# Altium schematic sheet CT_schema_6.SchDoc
size 255 x 159 mm
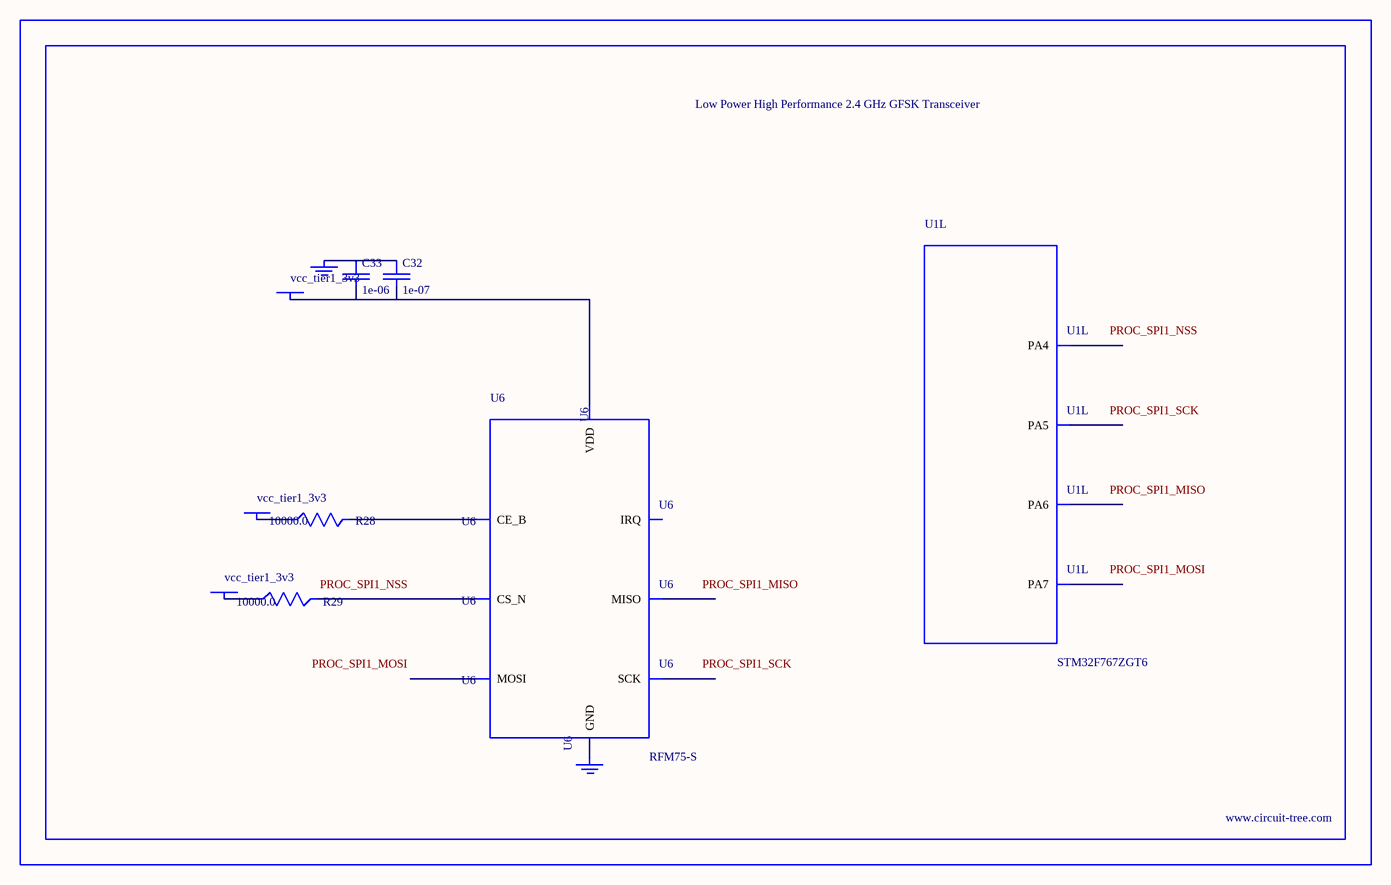
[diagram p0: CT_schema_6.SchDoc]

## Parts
BORDER5  (no value)
C32  1e-07  [C0402]
C33  1e-06  [C0603]
GND_INSTANCE_5_0  (no value)
GND_INSTANCE_5_1  (no value)
POWER_INSTANCE_5_0  vcc_tier1_3v3
POWER_INSTANCE_5_1  vcc_tier1_3v3
POWER_INSTANCE_5_2  vcc_tier1_3v3
R28  10000.0  [R0603]
R29  10000.0  [R0603]
U1  STM32F767ZGT6  [LQFP144]  (part L of 13)
U6  RFM75-S  [RFM75-S]

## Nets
NetC32_1: C32.1 C33.1 GND_INSTANCE_5_0.0(GND)
NetC32_2: C32.2 C33.2 POWER_INSTANCE_5_0.0(PWR) U6.2(VDD)
NetGND_INSTANCE_5_1_0: GND_INSTANCE_5_1.0(GND) U6.1(GND)
NetPOWER_INSTANCE_5_1_0: POWER_INSTANCE_5_1.0(PWR) R28.1
NetPOWER_INSTANCE_5_2_0: POWER_INSTANCE_5_2.0(PWR) R29.1
NetR28_2: R28.2 U6.3(CE_B)
NetR29_2: R29.2 U6.4(CS_N)

Not connected (* = marked no-connect by the designer): U1 40(PA4) 41(PA5) 42(PA6) 43(PA7); U6 5(SCK) 6(MOSI) 7(MISO) 8(IRQ)

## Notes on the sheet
- Labels drawn without touching a wire or pin: PROC_SPI1_MISO, PROC_SPI1_MOSI, PROC_SPI1_NSS, PROC_SPI1_SCK

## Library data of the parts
BORDER5 = BORDER_PAGE5
C32 = C0402C104K3RACTU
C33 = C0603C105K3RACTU
GND_INSTANCE_5_0 GND_INSTANCE_5_1 = GND
POWER_INSTANCE_5_0-POWER_INSTANCE_5_2 = PWR
R28 R29 = RC0603JR-0710KL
